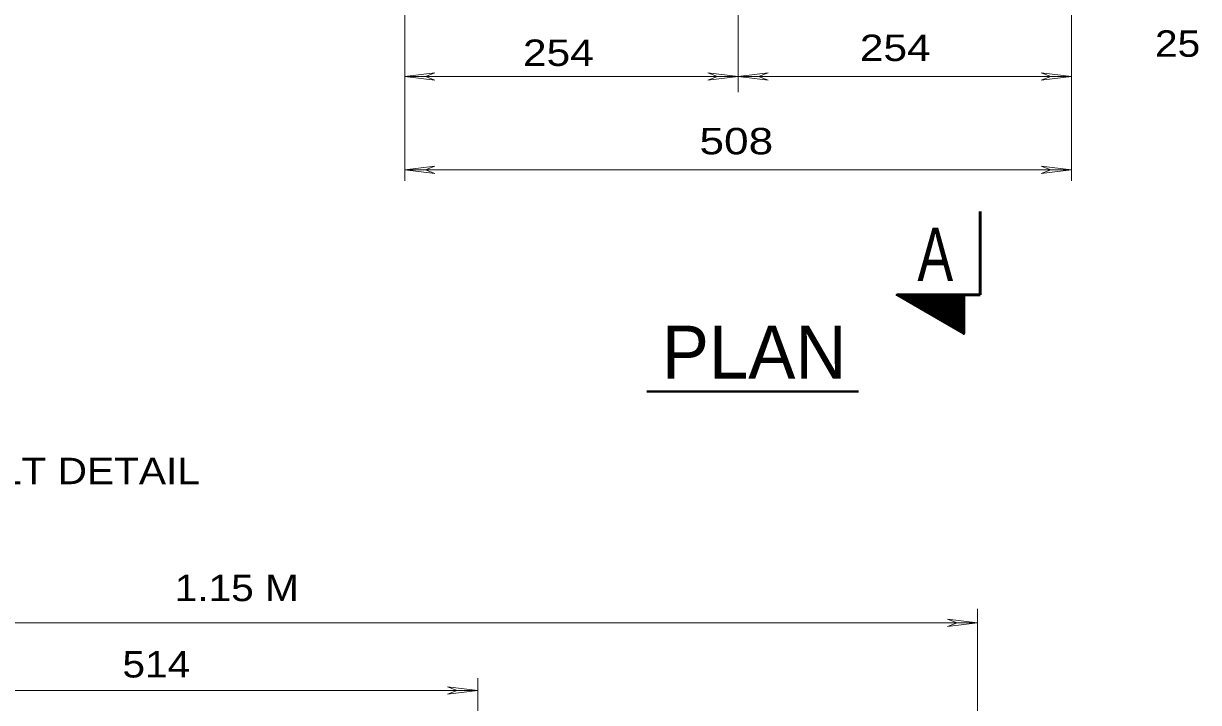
# Model space of a CAD drawing. Extents: x 312583 to 312854, y 144419 to 144597.
# Drawn here: x 312642.19 to 312675.97, y 144502.81 to 144522.33 of the extents above; entities that cross this region are included whole.
import ezdxf
from ezdxf.enums import TextEntityAlignment as Align

# ---------------------------------------------------------------- set-up
doc = ezdxf.new("R2010")
doc.units = 0
doc.header["$LTSCALE"] = 0.3
doc.layers.add('1', color=7, linetype='Continuous', lineweight=25)
doc.layers.add('2', color=7, linetype='Continuous', lineweight=13)

msp = doc.modelspace()

# ---------------------------------------------------------------- linework, layer by layer
at = {"layer": '1', "lineweight": 53}
for p in [(312669.695, 144516.9196), (312669.2197, 144514.5276)]:
    msp.add_line(p, (312669.695, 144514.5276), dxfattribs=at)
at = {"layer": '1', "lineweight": 35}
for p, q in [((312667.3184, 144514.5276), (312667.3184, 144514.5123)), ((312667.349, 144514.5276), (312667.3414, 144514.5046)), ((312667.3797, 144514.5276), (312667.3567, 144514.4893)), ((312667.4027, 144514.5276), (312667.3797, 144514.4816)), ((312667.4334, 144514.5276), (312667.4027, 144514.4663)), ((312667.4564, 144514.5276), (312667.418, 144514.4586)), ((312667.487, 144514.5276), (312667.441, 144514.4433)), ((312667.5177, 144514.5276), (312667.464, 144514.4356)), ((312667.5484, 144514.5276), (312667.4794, 144514.4203)), ((312667.5714, 144514.5276), (312667.5024, 144514.4126)), ((312667.5944, 144514.5276), (312667.5254, 144514.3973)), ((312667.625, 144514.5276), (312667.5484, 144514.3896)), ((312667.648, 144514.5276), (312667.5637, 144514.3743)), ((312667.6787, 144514.5276), (312667.5867, 144514.359)), ((312667.7094, 144514.5276), (312667.6097, 144514.3513)), ((312667.74, 144514.5276), (312667.625, 144514.336)), ((312667.763, 144514.5276), (312667.648, 144514.3206)), ((312667.7937, 144514.5276), (312667.671, 144514.313)), ((312667.8167, 144514.5276), (312667.6864, 144514.2976)), ((312667.8474, 144514.5276), (312667.7094, 144514.29)), ((312667.878, 144514.5276), (312667.7324, 144514.2746)), ((312667.901, 144514.5276), (312667.7477, 144514.267)), ((312667.9317, 144514.5276), (312667.7784, 144514.2516)), ((312667.9547, 144514.5276), (312667.7937, 144514.244)), ((312667.9854, 144514.5276), (312667.8167, 144514.2286)), ((312668.016, 144514.5276), (312667.8397, 144514.221)), ((312668.039, 144514.5276), (312667.855, 144514.2056)), ((312668.0697, 144514.5276), (312667.878, 144514.198)), ((312668.0927, 144514.5276), (312667.901, 144514.1826)), ((312668.1234, 144514.5276), (312667.9164, 144514.1673)), ((312668.1464, 144514.5276), (312667.9394, 144514.1596)), ((312668.177, 144514.5276), (312667.9624, 144514.1443)), ((312668.2077, 144514.5276), (312667.9777, 144514.129)), ((312668.2384, 144514.5276), (312668.0007, 144514.1213)), ((312668.2614, 144514.5276), (312668.0237, 144514.106)), ((312668.2844, 144514.5276), (312668.0467, 144514.0983)), ((312668.315, 144514.5276), (312668.062, 144514.083)), ((312668.3457, 144514.5276), (312668.085, 144514.0753)), ((312668.3687, 144514.5276), (312668.108, 144514.06)), ((312668.3994, 144514.5276), (312668.1234, 144514.0523)), ((312668.43, 144514.5276), (312668.1464, 144514.037)), ((312668.453, 144514.5276), (312668.1694, 144514.0293)), ((312668.4837, 144514.5276), (312668.1847, 144514.014)), ((312668.5144, 144514.5276), (312668.2077, 144514.0063)), ((312668.5374, 144514.5276), (312668.2307, 144513.991)), ((312668.568, 144514.52), (312668.246, 144513.9756)), ((312668.591, 144514.5276), (312668.2767, 144513.968)), ((312668.6217, 144514.5276), (312668.292, 144513.9526)), ((312668.6447, 144514.5276), (312668.315, 144513.945)), ((312668.6754, 144514.5276), (312668.338, 144513.9296)), ((312668.706, 144514.5276), (312668.3534, 144513.922)), ((312668.7367, 144514.5276), (312668.3764, 144513.9066)), ((312668.7597, 144514.5276), (312668.3994, 144513.899)), ((312668.7827, 144514.5276), (312668.4147, 144513.8836)), ((312668.8134, 144514.52), (312668.4377, 144513.876)), ((312668.844, 144514.5276), (312668.4607, 144513.8606)), ((312668.867, 144514.5276), (312668.476, 144513.853)), ((312668.8977, 144514.5276), (312668.499, 144513.8376)), ((312668.9284, 144514.5276), (312668.522, 144513.8223)), ((312668.9514, 144514.5276), (312668.545, 144513.8146)), ((312668.982, 144514.5276), (312668.5604, 144513.7993)), ((312669.0127, 144514.5276), (312668.5834, 144513.784)), ((312669.0357, 144514.52), (312668.6064, 144513.7763)), ((312669.0664, 144514.52), (312668.6217, 144513.761)), ((312669.0894, 144514.5276), (312668.6447, 144513.7533)), ((312669.12, 144514.5276), (312668.6677, 144513.738)), ((312669.143, 144514.5276), (312668.683, 144513.7303)), ((312669.1737, 144514.5276), (312668.706, 144513.715)), ((312669.2044, 144514.5276), (312668.729, 144513.7073)), ((312669.2197, 144514.5046), (312668.7444, 144513.692)), ((312669.2197, 144514.451), (312668.775, 144513.6843)), ((312669.2197, 144514.4126), (312668.7904, 144513.669)), ((312669.2197, 144514.359), (312668.8134, 144513.6613)), ((312669.2197, 144514.313), (312668.8364, 144513.646)), ((312669.2197, 144514.267), (312668.8517, 144513.6306)), ((312669.2197, 144514.221), (312668.8747, 144513.623)), ((312669.2197, 144514.1673), (312668.8977, 144513.6076)), ((312669.2197, 144514.1213), (312668.913, 144513.5923)), ((312669.2197, 144514.0753), (312668.936, 144513.5846)), ((312669.2197, 144514.0216), (312668.9514, 144513.5693)), ((312669.2197, 144513.9756), (312668.9744, 144513.5616)), ((312669.2197, 144513.9296), (312668.9974, 144513.5463)), ((312669.2197, 144513.876), (312669.0127, 144513.5386)), ((312669.2197, 144513.83), (312669.0434, 144513.5233)), ((312669.2197, 144513.784), (312669.0587, 144513.5156)), ((312669.2197, 144513.738), (312669.0817, 144513.5003)), ((312669.2197, 144513.6843), (312669.1047, 144513.4926)), ((312669.2197, 144513.646), (312669.12, 144513.4773)), ((312669.2197, 144513.5923), (312669.143, 144513.4696)), ((312669.2197, 144513.5463), (312669.166, 144513.4543)), ((312669.2197, 144513.4926), (312669.1814, 144513.439)), ((312669.2197, 144513.4466), (312669.2044, 144513.4313))]:
    msp.add_line(p, q, dxfattribs=at)
at = {"layer": '1', "lineweight": 53}
msp.add_lwpolyline([(312669.2197, 144514.5276), (312669.2197, 144513.416), (312667.303, 144514.5276)], close=True, dxfattribs=at)
at = {"layer": '2'}
for p, q in [((312662.7337, 144530.9496), (312662.7337, 144520.3543)), ((312653.1504, 144525.284), (312653.1504, 144517.809)), ((312672.317, 144524.847), (312672.317, 144517.809)), ((312653.1504, 144520.8066), (312654.0167, 144520.914)), ((312653.1504, 144520.8066), (312654.0167, 144520.6993)), ((312654.0167, 144520.914), (312653.7407, 144520.8066)), ((312654.0167, 144520.6993), (312653.7407, 144520.8066)), ((312661.8674, 144520.914), (312662.1434, 144520.8066)), ((312662.7337, 144520.8066), (312661.8674, 144520.914)), ((312661.8674, 144520.6993), (312662.1434, 144520.8066)), ((312662.7337, 144520.8066), (312661.8674, 144520.6993)), ((312662.7337, 144520.8066), (312663.6, 144520.914)), ((312662.7337, 144520.8066), (312663.6, 144520.6993)), ((312663.6, 144520.914), (312663.324, 144520.8066)), ((312663.6, 144520.6993), (312663.324, 144520.8066)), ((312671.4507, 144520.914), (312671.7267, 144520.8066)), ((312672.317, 144520.8066), (312671.4507, 144520.914)), ((312671.4507, 144520.6993), (312671.7267, 144520.8066)), ((312672.317, 144520.8066), (312671.4507, 144520.6993)), ((312653.1504, 144518.1233), (312654.0167, 144518.2306)), ((312653.1504, 144518.1233), (312672.317, 144518.1233)), ((312653.1504, 144518.1233), (312654.0167, 144518.016)), ((312654.0167, 144518.2306), (312653.7407, 144518.1233)), ((312654.0167, 144518.016), (312653.7407, 144518.1233)), ((312671.4507, 144518.2306), (312671.7267, 144518.1233)), ((312672.317, 144518.1233), (312671.4507, 144518.2306)), ((312671.4507, 144518.016), (312671.7267, 144518.1233)), ((312672.317, 144518.1233), (312671.4507, 144518.016)), ((312669.6198, 144494.5871), (312669.6198, 144505.4968)), ((312668.7535, 144505.2054), (312669.0295, 144505.0981)), ((312669.6198, 144505.0981), (312668.7535, 144505.2054)), ((312626.2571, 144505.0981), (312669.6198, 144505.0981)), ((312668.7535, 144504.9908), (312669.0295, 144505.0981)), ((312669.6198, 144505.0981), (312668.7535, 144504.9908)), ((312655.2448, 144490.6388), (312655.2448, 144503.5034)), ((312635.8405, 144503.1508), (312655.2448, 144503.1508)), ((312654.3785, 144503.2581), (312654.6545, 144503.1508)), ((312655.2448, 144503.1508), (312654.3785, 144503.2581)), ((312654.3785, 144503.0434), (312654.6545, 144503.1508)), ((312655.2448, 144503.1508), (312654.3785, 144503.0434))]:
    msp.add_line(p, q, dxfattribs=at)
at = {"layer": '2', "lineweight": 40}
msp.add_line((312660.1047, 144511.7446), (312666.1993, 144511.7446), dxfattribs=at)
at = {"layer": '2'}
msp.add_lwpolyline([(312653.1504, 144520.8066), (312662.7337, 144520.8066), (312672.317, 144520.8066)], dxfattribs=at)

# ---------------------------------------------------------------- texts
at = {"layer": '1', "width": 0.75}
msp.add_text('A', height=1.533, dxfattribs=at).set_placement((312668.4032, 144514.9263), align=Align.CENTER)
at = {"layer": '2'}
for s, width, p in [('25 ', 1.15, (312674.7211, 144521.3729)), ('254 ', 1.2, (312656.5482, 144521.1094)), ('254 ', 1.2, (312666.235, 144521.2513)), ('508 ', 1.25, (312661.6224, 144518.568)), ('FOR BOLT DETAIL', 1.15, (312636.9981, 144509.0838)), ('1.15 M', 1.15, (312646.5317, 144505.7201)), ('514 ', 1.15, (312645.0295, 144503.5246))]:
    msp.add_text(s, height=0.76, dxfattribs=dict(at, width=width)).set_placement(p)
msp.add_text('PLAN', height=1.52, dxfattribs=at).set_placement((312663.1941, 144512.1204), align=Align.CENTER)

doc.saveas('drawing.dxf')
